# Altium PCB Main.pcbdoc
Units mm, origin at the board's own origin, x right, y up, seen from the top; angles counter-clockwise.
Board outline 147.89 x 80.52 mm, 2 copper layers (Top Layer, Bottom Layer); 32 components, 18 nets, 91 pads, 27 vias.
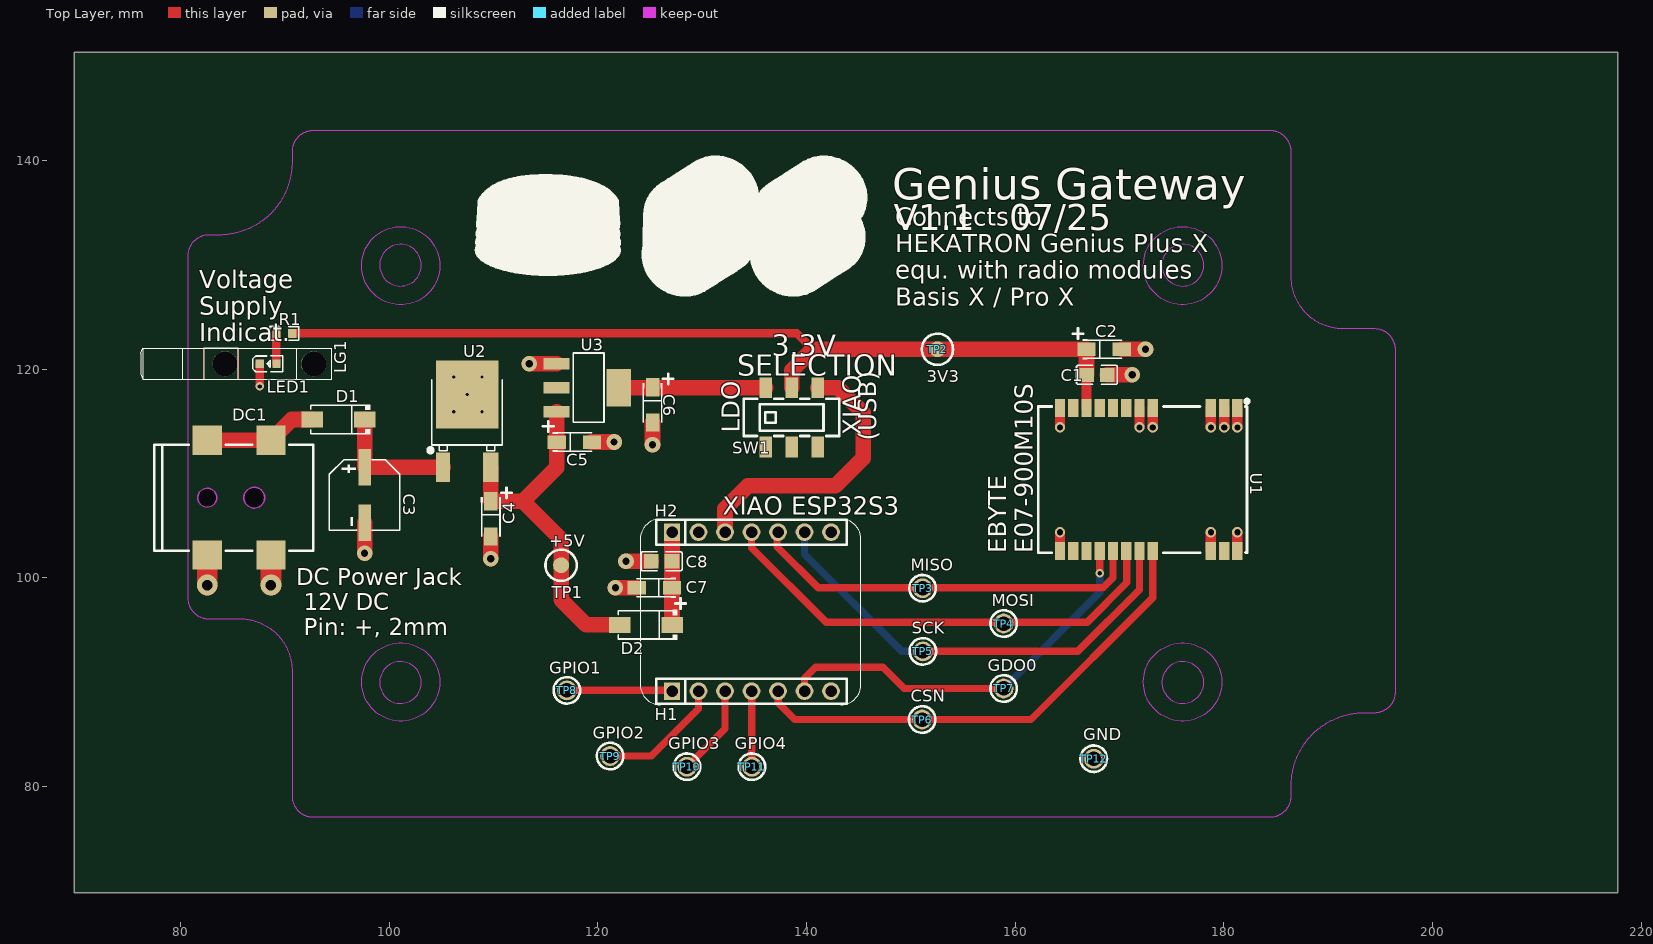
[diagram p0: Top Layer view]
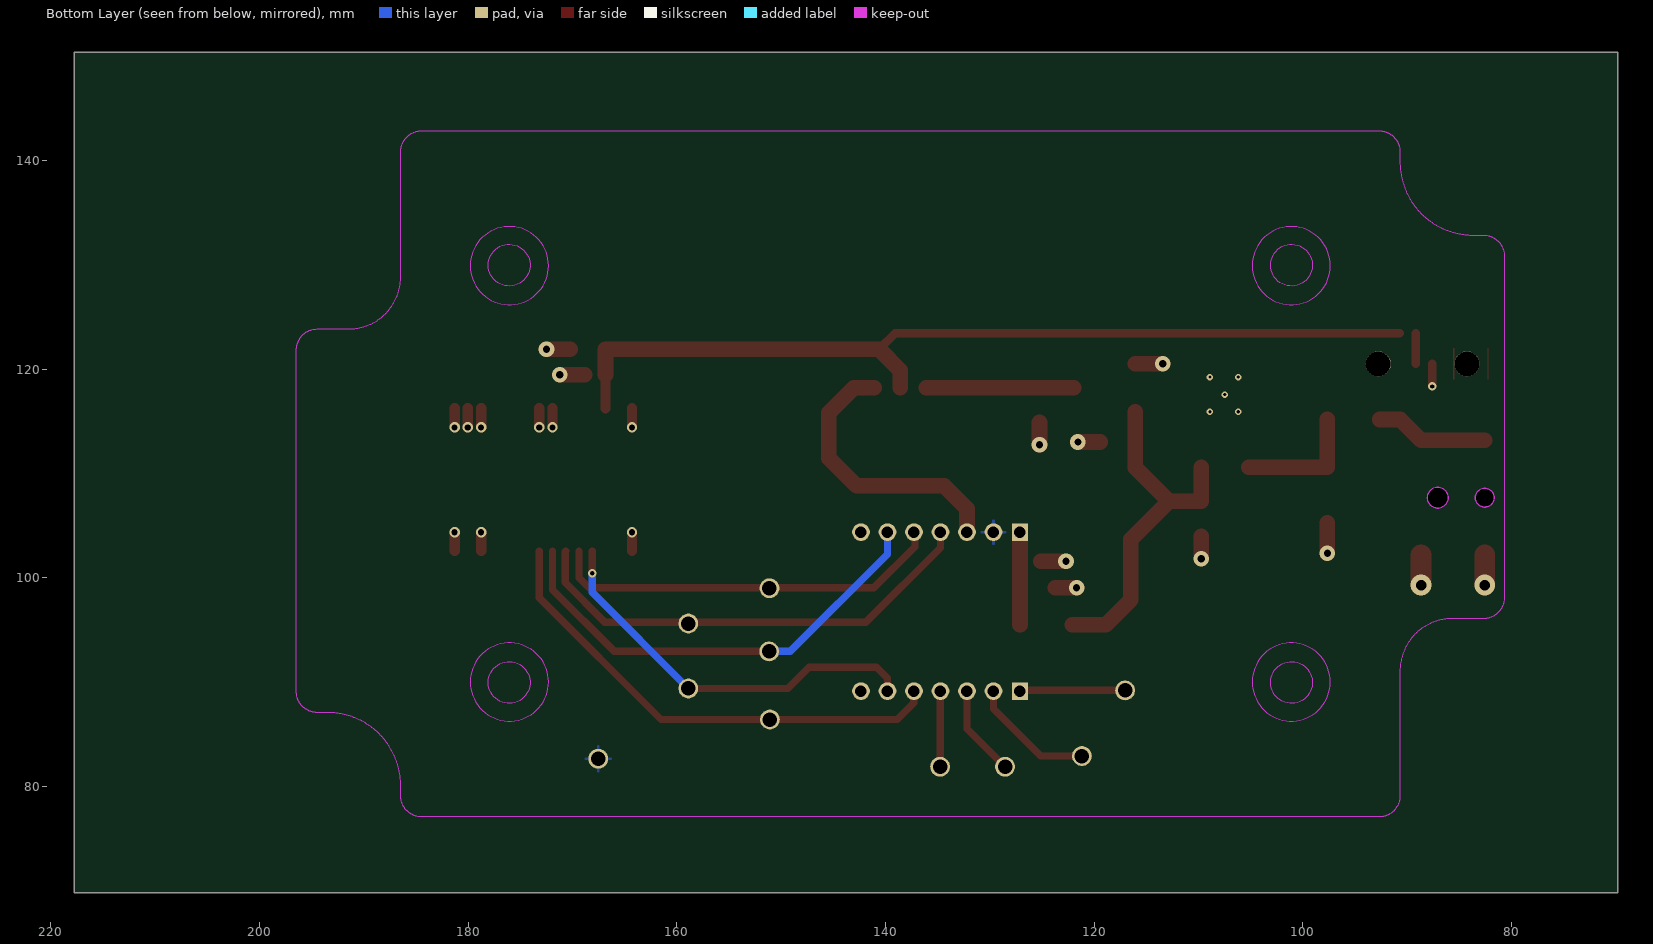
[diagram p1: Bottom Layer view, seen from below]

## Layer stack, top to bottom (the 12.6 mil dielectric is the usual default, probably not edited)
Top Layer: signal copper (thickness not stored)
Dielectric: dielectric 0.32, FR-4, Dk 4.8
Bottom Layer: signal copper (thickness not stored)

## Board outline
217.744,69.85 69.85,69.85 69.85,150.368 217.744,150.368

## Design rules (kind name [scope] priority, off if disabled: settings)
BoardOutlineClearance copperThickness1oz [All] p0: genericclearance=0.254 ignorepadtopadclearanceinfootprint=FALSE except(0: Arc-SplitContinuation Track-SplitContinuation SMDPad-SplitContinuation THPad-SplitContinuation Via-SplitContinuation Fill-SplitContinuation Poly-SplitContinuation Region-SplitContinuation Text-SplitContinuation; 0.152: Track-CutoutEdge SMDPad-CutoutEdge THPad-CutoutEdge Via-CutoutEdge Region-CutoutEdge; 0.3: Track-OutlineEdge SMDPad-OutlineEdge THPad-OutlineEdge Via-OutlineEdge Fill-OutlineEdge Region-OutlineEdge Poly-OutlineEdge Text-OutlineEdge Fill-CutoutEdge)
BoardOutlineClearance copperThickness2oz [All] p0: genericclearance=0.254 ignorepadtopadclearanceinfootprint=FALSE except(0: Arc-SplitContinuation Track-SplitContinuation SMDPad-SplitContinuation THPad-SplitContinuation Via-SplitContinuation Fill-SplitContinuation Poly-SplitContinuation Region-SplitContinuation Text-SplitContinuation; 0.152: Track-CutoutEdge SMDPad-CutoutEdge THPad-CutoutEdge Via-CutoutEdge Region-CutoutEdge; 0.3: Track-OutlineEdge SMDPad-OutlineEdge THPad-OutlineEdge Via-OutlineEdge Fill-OutlineEdge Region-OutlineEdge Poly-OutlineEdge Text-OutlineEdge Fill-CutoutEdge)
Clearance copperThickness1oz [(InNet('+12V') OR InNet('GND') OR InNet('$1N1660') OR InNet('+5V') OR InNet('+12V_IN') OR InNet('+3V3') OR InNet('+3V3-LDO') OR InNet('+3V3-XIAO') OR InNet('SCK') OR InNet('MISO') OR InNet('MOSI') OR InNet('GDO0') OR InNet('CSN') OR InNet('GPIO4') OR InNet('GPIO3') OR InNet('GPIO2') OR InNet('GPIO1') OR InNet('$1N5727'))] p1: gap=0.178 ignorepadtopadclearanceinfootprint=FALSE except(0.102: Track-Track; 0.152: Track-SMDPad SMDPad-SMDPad Track-THPad SMDPad-THPad THPad-THPad Track-Via SMDPad-Via THPad-Via Via-Via SMDPad-Fill THPad-Fill Via-Fill Fill-Fill Track-Region SMDPad-Region THPad-Region Via-Region Region-Region Track-Poly SMDPad-Poly THPad-Poly Via-Poly Fill-Poly Region-Poly Poly-Poly Track-Text SMDPad-Text THPad-Text Via-Text Fill-Text Region-Text Poly-Text Text-Text; 0.175: Track-Hole SMDPad-Hole THPad-Hole Via-Hole Fill-Hole Region-Hole Poly-Hole Text-Hole Sheet-Hole; 0.3: Track-Fill Fill-Region Track-Sheet SMDPad-Sheet THPad-Sheet Via-Sheet Fill-Sheet Region-Sheet Poly-Sheet Text-Sheet)
Clearance copperThickness2oz [All] p1: gap=0.178 ignorepadtopadclearanceinfootprint=FALSE except(0.152: Track-SMDPad SMDPad-SMDPad Track-THPad SMDPad-THPad THPad-THPad Track-Via SMDPad-Via THPad-Via Via-Via SMDPad-Fill THPad-Fill Via-Fill Fill-Fill Track-Region SMDPad-Region THPad-Region Via-Region Region-Region Track-Poly SMDPad-Poly THPad-Poly Via-Poly Fill-Poly Region-Poly Poly-Poly Track-Text SMDPad-Text THPad-Text Via-Text Fill-Text Region-Text Poly-Text Text-Text; 0.175: Track-Hole SMDPad-Hole THPad-Hole Via-Hole Fill-Hole Region-Hole Poly-Hole Text-Hole Sheet-Hole; 0.203: Track-Track; 0.3: Track-Fill Fill-Region Track-Sheet SMDPad-Sheet THPad-Sheet Via-Sheet Fill-Sheet Region-Sheet Poly-Sheet Text-Sheet)
DiffPairsRouting differentialPair [All] p1: maxuncoupledlength=10 minlimit=6 maxlimit=6 mostfreqgap=6 toplayer_minwidth=5 toplayer_prefwidth=10 toplayer_maxwidth=100 bottomlayer_minwidth=5 bottomlayer_prefwidth=10 bottomlayer_maxwidth=100
PasteMaskExpansion pasteMaskExpansion [All] p1: expansion=0
PlaneConnect innerPlane [All] p1: planeconnectstyle=Relief reliefexpansion=0.508 reliefentries=4 reliefconductorwidth=0.254 reliefairgap=0.254
PolygonConnect copperRegion [All] p1: connectstyle=Relief reliefentries=4 reliefconductorwidth=10 polygonreliefangle="90 Angle" airgapwidth=10
RoutingVias viaSize [All] p1: viastyle="Through Hole" holewidth=12.0078 minholewidth=11.811 maxholewidth=248.0314 width=24.0158 minwidth=19.685 maxwidth=393.7008
SolderMaskExpansion solderMaskExpansion [All] p1: useseparateexpansions=TRUE expansion=2 expansionbottom=2
Width copperThickness1oz [All] p1: maxlimit=100 minlimit=5 preferedwidth=10
Width copperThickness2oz [All] p1: maxlimit=100 minlimit=8 preferedwidth=10

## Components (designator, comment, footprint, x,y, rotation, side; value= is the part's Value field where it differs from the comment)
C1 "CC0805KRX7R9BB104" C0805 167.848,119.466 r180 top
C2 "TAJA106K016RNJ" CAP-SMD_L3.2-W1.6-RD-C7171 168.534,121.92 r0 top
C3 "189RV0016" CAP-SMD_BD6.3-L6.6-W6.6-LS7.6-RD 97.658,107.95 r270 top
C4 "TAJA106K016RNJ" CAP-SMD_L3.2-W1.6-RD-C7171 109.759,105.664 r270 top
C5 "TAJA106K016RNJ" CAP-SMD_L3.2-W1.6-RD-C7171 117.76,113.03 r0 top
C6 "TAJA106K016RNJ" CAP-SMD_L3.2-W1.6-RD-C7171 125.253,116.586 r270 top
C7 "TAJA106K016RNJ" CAP-SMD_L3.2-W1.6-RD-C7171 125.435,99.06 r180 top
C8 "CC0805KRX7R9BB104" C0805 126.122,101.6 r0 top
D1 "SS54_C22452" SMA_L4.4-W2.8-LS5.4-R-RD 95.154,115.189 r180 top
D2 "SS54_C22452" SMA_L4.4-W2.8-LS5.4-R-RD 124.618,95.504 r180 top
DC1 "DC-005-5A-2.0-SMT" DC-IN-TH_DC-005-5A-2.0-SMT 85.629,107.696 r0 top
H1 "PM254-1-07-Z-8.5" HDR-TH_7P-P2.54-V-F 134.742,89.154 r0 top
H2 "PM254-1-07-Z-8.5" HDR-TH_7P-P2.54-V-F 134.742,104.394 r0 top
LED1 "KT-0603R" LED0603-RD 88.413,120.523 r0 top
LG1 "Lightguide 1" MENTOR-1271.1000 88.09,120.523 r90 top
R1 "0603WAF5600T5E" R0603 89.966,123.444 r0 top
SW1 "MST22D18G2 125" SW-SMD_MST22D18G2 138.588,115.387 r0 top
TP1 "+5V" Testpoint_SMD_R1.5_Border 116.49,101.219 r0 top
TP2 "3V3" Testpoint_SMD_R1.5_Border 152.558,121.92 r0 top
TP3 "MISO" TEST-TH_BD2.54-P1.39 151.134,99.021 r90 top
TP4 "MOSI" TEST-TH_BD2.54-P1.39 158.908,95.631 r90 top
TP5 "SCK" TEST-TH_BD2.54-P1.39 151.161,92.964 r90 top
TP6 "CSN" TEST-TH_BD2.54-P1.39 151.096,86.433 r90 top
TP7 "GDO0" TEST-TH_BD2.54-P1.39 158.908,89.408 r90 top
TP8 "GPIO1" TEST-TH_BD2.54-P1.39 117.044,89.227 r90 top
TP9 "GPIO2" TEST-TH_BD2.54-P1.39 121.189,82.931 r90 top
TP10 "GPIO3" TEST-TH_BD2.54-P1.39 128.555,81.915 r90 top
TP11 "GPIO4" TEST-TH_BD2.54-P1.39 134.778,81.915 r90 top
TP12 "GND" TEST-TH_BD2.54-P1.39 167.544,82.677 r90 top
U1 "E07-900M10S" WIRELM-SMD_22P-L20.0-W14.0-P1.27-BR 172.808,109.433 r90 top
U2 "L78M05ABDT-TR" TO-252-2_L6.5-W6.1-P4.58-LS10.0-TL 107.473,114.095 r90 top
U3 "AMS1117-3.3_C6186" SOT-223-3_L6.5-W3.4-P2.30-LS7.0-BR 119.03,118.237 r180 top

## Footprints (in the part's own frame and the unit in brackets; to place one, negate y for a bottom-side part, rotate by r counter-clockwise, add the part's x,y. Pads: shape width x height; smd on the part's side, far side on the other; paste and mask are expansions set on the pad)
C0805 [mm]
  rect 1.41x1.35 smd: 1(-1,0) 2(1,0)
  silkscreen extent -1.96,-0.9 1.96,0.9
CAP-SMD_BD6.3-L6.6-W6.6-LS7.6-RD [mm]
  rect 3.5x1.2 smd: 1(-2.67,0) 2(2.67,0)
  silkscreen extent -3.38,-3.38 3.38,3.38
CAP-SMD_L3.2-W1.6-RD-C7171 [mm]
  rect 1.758x1.296 smd: 1(-1.686,0) 2(1.686,0)
  silkscreen extent -3,-0.95 1.68,2
DC-IN-TH_DC-005-5A-2.0-SMT [mm]
  rect 2.8x2.8 smd: 1(-3.05,5.5) 1(3.05,5.5) 2(-3.05,-5.5) 3(3.05,-5.5)
  Board Outline Layer circle w0.005: c1.45,0 r1
  Board Outline Layer circle w0.005: c-3.05,0 r0.9
  Board Outline Layer region: 2.45,0 2.351,-0.434 2.073,-0.782 1.672,-0.975 1.227,-0.975 0.826,-0.782 0.549,-0.434 0.45,0 0.45,0 0.549,0.434 0.826,0.782 1.227,0.975 1.672,0.975 2.073,0.782 2.351,0.434 2.45,0
  Board Outline Layer region: -2.15,0 -2.239,-0.39 -2.489,-0.703 -2.85,-0.877 -3.25,-0.877 -3.611,-0.703 -3.861,-0.39 -3.95,0 -3.95,0 -3.861,0.391 -3.611,0.704 -3.25,0.878 -2.85,0.878 -2.489,0.704 -2.239,0.391 -2.15,0
  Multi-Layer board cut-out: 2.45,0 2.351,-0.434 2.073,-0.782 1.672,-0.975 1.227,-0.975 0.826,-0.782 0.549,-0.434 0.45,0 0.45,0 0.549,0.434 0.826,0.782 1.227,0.975 1.672,0.975 2.073,0.782 2.351,0.434 2.45,0
  Multi-Layer board cut-out: -2.15,0 -2.239,-0.39 -2.489,-0.703 -2.85,-0.877 -3.25,-0.877 -3.611,-0.703 -3.861,-0.39 -3.95,0 -3.95,0 -3.861,0.391 -3.611,0.704 -3.25,0.878 -2.85,0.878 -2.489,0.704 -2.239,0.391 -2.15,0
  silkscreen extent -8.13,-5.08 7.11,5.08
HDR-TH_7P-P2.54-V-F [mm]
  rect 1.575x1.7 hole 1.1: 1(-7.62,0)
  round 1.7 hole 1.1: 2(-5.08,0) 3(-2.54,0) 4(0,0) 5(2.54,0) 6(5.08,0) 7(7.62,0)
  silkscreen extent -9.13,-1.2 9.13,1.2
LED0603-RD [mm]
  rect 0.8x0.8 smd: 1(-0.799,0) 2(0.799,0)
  silkscreen extent -1.49,-0.75 1.39,0.76
MENTOR-1271.1000 [mm]
  round 2.4 hole 2.4 unplated: 0(0,3.8) 0(0,-4.7)
  Top Layer lines w0.1: -1.5,5.84 1.5,5.84 ; -1.5,2.54 1.5,2.54 ; -1.5,2.54 1.5,2.54 ; -1.5,2.54 1.5,2.54
  silkscreen extent -1.5,-6.4 1.5,11.89
R0603 [mm]
  rect 0.806x0.864 smd: 1(-0.753,0) 2(0.753,0)
  silkscreen extent -1.39,-0.66 1.39,0.66
SMA_L4.4-W2.8-LS5.4-R-RD [mm]
  rect 2.063x1.539 smd: 1(2.504,0) 2(-2.504,0)
  silkscreen extent -3.03,-1.43 2.65,1.43
SOT-223-3_L6.5-W3.4-P2.30-LS7.0-BR [mm]
  rect 2.5x1.1 smd: 1(2.97,-2.3) 2(2.97,0) 3(2.97,2.3)
  rect 2.34x3.6 smd: 4(-2.97,0)
  silkscreen extent -1.57,-3.33 1.37,3.33
SW-SMD_MST22D18G2 [mm]
  rect 1.2x2 smd: 1(-2.5,2.85) 2(0,2.85) 3(2.5,2.85) 4(-2.5,-2.85) 5(0,-2.85) 6(2.5,-2.85)
  silkscreen extent -4.6,-1.78 4.57,1.8
TEST-TH_BD2.54-P1.39 [mm]
  round 1.9 hole 1.39: 1(0,0)
  silkscreen extent -1.27,-1.27 1.27,1.27
Testpoint_SMD_R1.5_Border [mil]
  round 60 smd: 1(0,0)
  silkscreen extent -59,-59 59,59
TO-252-2_L6.5-W6.1-P4.58-LS10.0-TL [mm]
  rect 2.8x1.35 smd: 1(-3.475,2.29)
  rect 2.8x1.5 smd: 3(-3.475,-2.29)
  rect 6.5x6 smd: 4(3.475,-0.017)
  silkscreen extent -2.06,-3.39 4.9,3.7
WIRELM-SMD_22P-L20.0-W14.0-P1.27-BR [mm]
  rect 1.7x1 smd: 1(6.85,-8.5) 2(6.85,-7.23) 3(6.85,-5.96) 4(6.85,-0.39) 5(6.85,0.88) 6(6.85,2.15) 7(6.85,3.42) 8(6.85,4.69) 9(6.85,5.96) 10(6.85,7.23) 11(6.85,8.5) 12(-6.85,8.5) 13(-6.85,7.23) 14(-6.85,5.96) 15(-6.85,4.69) 16(-6.85,3.42) 17(-6.85,2.15) 18(-6.85,0.88) 19(-6.85,-0.39) 20(-6.85,-5.96) 21(-6.85,-7.23) 22(-6.85,-8.5)
  silkscreen extent -7,-9.59 7.67,10.58

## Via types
v1: diameter 1, hole 0.6, Top Layer to Bottom Layer, 9 vias
v2: diameter 1.5, hole 0.7, Top Layer to Bottom Layer, 9 vias
v3: diameter 0.61, hole 0.305, Top Layer to Bottom Layer, 5 vias
v4: diameter 0.8, hole 0.4, Top Layer to Bottom Layer, 2 vias
v5: diameter 2, hole 1, Top Layer to Bottom Layer, 2 vias

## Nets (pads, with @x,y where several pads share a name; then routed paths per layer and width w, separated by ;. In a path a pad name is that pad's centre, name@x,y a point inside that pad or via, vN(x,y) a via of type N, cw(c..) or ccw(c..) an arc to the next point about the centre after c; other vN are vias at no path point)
$1N1660: C7.1 C8.2 D2.2 H2.1 | length 8.9
  Top Layer w1.5: D2.2 C7.1 C8.2 H2.1
$1N5727: LED1.2 R1.1 | length 2.9
  Top Layer w0.8: LED1.2@89.206,120.523 R1.1@89.206,123.444
+3V3: C1.2 C2.1 R1.2 SW1.2 TP2.1 U1.9 | length 86.9
  Top Layer w0.8: R1.2@90.713,123.444 139.096,123.444 140.62,121.92
  Top Layer w1: U1.9 C1.2
  Top Layer w1.5: SW1.2 138.588,119.888 140.62,121.92 TP2.1 161.702,121.92 C2.1@166.808,121.92 ; C1.2 C2.1
+3V3-LDO: C6.1 SW1.1 U3.4 | length 14.1
  Top Layer w1.5: U3.4 125.253,118.237 SW1.1
+3V3-XIAO: H2.3 SW1.3 | length 27.2
  Top Layer w1.5: H2.3 132.202,106.644 134.397,108.839 142.779,108.839 145.446,111.506 145.446,115.824 143.033,118.237 SW1.3
+5V: C4.1 C5.1 D2.1 TP1.1 U2.3 U3.3 | length 33.9
  Top Layer w1.5: U2.3 109.763,107.354 C4.1 112.842,107.35 ; U3.3 116.06,113.044 C5.1 116.074,110.582 112.842,107.35 ; D2.1 118.903,95.504 116.49,97.917 116.49,100.838 116.49,103.703 112.842,107.35
+12V: C3.1 D1.2 U2.1 | length 12.1
  Top Layer w1.5: D1.2 C3.1 U2.1
+12V_IN: D1.1 DC1.1 | length 10.9
  Top Layer w1.5: DC1.1@82.579,113.196 88.679,113.196 90.672,115.189 D1.1
CSN: H1.5 TP6.1 U1.19 | length 47.1
  Top Layer w0.7: H1.5@137.318,89.281 137.318,88.011 138.842,86.487 138.896,86.433 TP6.1 161.52,86.433 161.575,86.487 173.198,98.11 U1.19
GDO0: H1.6 TP7.1 U1.15 | length 38.6
  Top Layer w0.7: H1.6 139.822,90.388 140.874,91.44 147.351,91.44 149.383,89.408 TP7.1 ; v4(168.118,100.457) U1.15
  Bottom Layer w0.7: TP7.1 168.118,98.618 v4(168.118,100.457)
GND: C1.1 C2.2 C3.2 C4.2 C5.2 C6.2 C7.2 C8.1 DC1.2 DC1.3 H2.2 LED1.1 TP12.1 U1.1 U1.2 U1.3 U1.4 U1.5 U1.11 U1.12 U1.20 U1.22 U2.4 U3.1 | length 45.5
  Top Layer w0.8: v4(87.607,118.364) LED1.1@87.607,120.523
  Top Layer w1: U1.12 v1(164.308,104.394) ; v1(164.308,114.427) U1.11 ; v1(171.928,114.427) U1.5 ; v1(173.198,114.427) U1.4 ; U1.20 v1(178.768,104.394) ; v1(178.768,114.427) U1.3 ; v1(180.038,114.427) U1.2 ; U1.22 v1(181.308,104.394) ; v1(181.308,114.427) U1.1
  Top Layer w1.5: v2(97.658,102.362) C3.2 ; v2(109.759,101.854) C4.2 ; v2(113.442,120.537) U3.1 ; C5.2 v2(121.57,113.03) ; v2(121.697,99.06) C7.2 ; v2(122.713,101.6) C8.1 ; v2(125.253,112.776) C6.2 ; C1.1 v2(171.227,119.466) ; C2.2 v2(172.497,121.92)
  Top Layer w2: DC1.2 82.581,102.194 v5(82.581,99.314) ; v5(88.679,99.314) DC1.3
  other v3: 106.203,115.928 108.923,115.928 107.49,117.57 106.203,119.253 108.923,119.253
GPIO1: H1.1 TP8.1 | length 10.1
  Top Layer w0.7: TP8.1 127.049,89.227 H1.1
GPIO2: H1.2 TP9.1 | length 12
  Top Layer w0.7: TP9.1 125.126,82.931 129.662,87.467 H1.2
GPIO3: H1.3 TP10.1 | length 8.7
  Top Layer w0.7: TP10.1 132.202,85.562 H1.3
GPIO4: H1.4 TP11.1 | length 7.3
  Top Layer w0.7: H1.4 134.778,89.118 TP11.1
MISO: H2.5 TP3.1 U1.16 | length 38.2
  Top Layer w0.7: H2.5 137.191,104.303 137.191,102.997 141.128,99.06 168.433,99.06 169.388,100.015 U1.16
MOSI: H2.4 TP4.1 U1.17 | length 45
  Top Layer w0.7: H2.4 134.742,102.906 141.89,95.758 166.909,95.758 170.719,99.568 170.719,102.523 U1.17
SCK: H2.6 TP5.1 U1.18 | length 44.2
  Top Layer w0.7: TP5.1 166.02,92.964 171.928,98.872 U1.18
  Bottom Layer w0.7: H2.6 139.822,102.271 149.129,92.964 TP5.1
pads on no net: H1.7 H2.7 LG1.0 SW1.4 SW1.5 SW1.6 U1.6 U1.7 U1.8 U1.10 U1.13 U1.14 U1.21 U3.2

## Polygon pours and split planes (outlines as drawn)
GND on Bottom Layer (solid, remove dead copper, pour order 0): 79.279,144.018 197.262,144.018 197.262,76.2 79.279,76.2

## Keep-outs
Board Outline Layer:
  circle w0.1: c176.078,129.981 r2
  circle w0.1: c176.078,89.983 r2
  circle w0.1: c101.098,129.981 r2
  circle w0.1: c101.098,89.983 r2
  region: 179.803,129.933 cw(c176.053,129.933) 172.303,129.933 cw(c176.053,129.933)
  region: 104.873,129.933 cw(c101.123,129.933) 97.373,129.933 cw(c101.123,129.933)
  region: 104.873,90.031 cw(c101.123,90.031) 97.373,90.031 cw(c101.123,90.031)
  region: 179.803,90.031 cw(c176.053,90.031) 172.303,90.031 cw(c176.053,90.031)
  lines w0.1: 80.708,98.033 80.707,98.097 80.707,130.866 80.708,130.93 80.711,130.994 80.716,131.058 80.723,131.122 80.732,131.185 80.744,131.248 80.757,131.311 80.772,131.373 80.789,131.435 80.809,131.496 80.83,131.557 80.853,131.616 80.878,131.675 80.905,131.734 80.933,131.791 80.964,131.847 80.997,131.902 81.031,131.956 81.067,132.008 81.105,132.059 81.145,132.11 81.186,132.158 81.229,132.206 81.273,132.252 81.319,132.297 81.366,132.34 81.414,132.382 81.463,132.422 81.514,132.461 81.566,132.499 81.619,132.534 81.674,132.568 81.729,132.601 81.785,132.632 81.842,132.66 81.9,132.688 81.959,132.713 82.018,132.737 82.078,132.758 82.139,132.778 82.2,132.796 82.262,132.812 82.325,132.826 82.387,132.838 82.45,132.847 82.514,132.855 82.578,132.861 82.641,132.864 82.706,132.865 83.709,132.865 83.808,132.866 83.907,132.868 84.005,132.872 84.104,132.877 84.203,132.883 84.302,132.891 84.4,132.901 84.499,132.912 84.597,132.924 84.695,132.937 84.792,132.953 84.89,132.969 84.987,132.987 85.084,133.006 85.181,133.027 85.278,133.049 85.374,133.072 85.47,133.096 85.565,133.122 85.66,133.15 85.755,133.178 85.849,133.208 85.943,133.239 86.037,133.272 86.13,133.306 86.222,133.341 86.315,133.377 86.406,133.415 86.497,133.454 86.588,133.494 86.678,133.535 86.767,133.578 86.856,133.622 86.944,133.667 87.031,133.713 87.118,133.76 87.205,133.809 87.29,133.859 87.375,133.91 87.459,133.962 87.542,134.015 87.625,134.07 87.707,134.126 87.788,134.182 87.868,134.24 87.947,134.299 88.026,134.359 88.104,134.421 88.18,134.483 88.256,134.546 88.331,134.611 88.405,134.677 88.478,134.743 88.55,134.811 88.622,134.88 88.692,134.95 88.761,135.021 88.829,135.092 88.896,135.165 88.962,135.239 89.026,135.314 89.09,135.39 89.153,135.467 89.214,135.544 89.275,135.623 89.334,135.702 89.392,135.782 89.449,135.863 89.504,135.945 89.559,136.027 89.612,136.111 89.665,136.195 89.716,136.28 89.765,136.365 89.814,136.451 89.861,136.538 89.908,136.626 89.953,136.714 89.996,136.803 90.039,136.892 90.08,136.982 90.12,137.073 90.159,137.164 90.197,137.255 90.233,137.347 90.268,137.44 90.302,137.533 90.334,137.627 90.365,137.721 90.395,137.815 90.423,137.91 90.45,138.005 90.476,138.101 90.501,138.197 90.524,138.293 90.546,138.389 90.566,138.486 90.585,138.583 90.603,138.681 90.619,138.778 90.634,138.876 90.648,138.974 90.66,139.072 90.671,139.171 90.68,139.269 90.688,139.368 90.695,139.467 90.7,139.566 90.703,139.665 90.705,139.764 90.706,139.863 90.706,140.866 90.707,140.93 90.71,140.994 90.716,141.058 90.723,141.121 90.732,141.185 90.743,141.248 90.757,141.311 90.772,141.373 90.789,141.435 90.808,141.496 90.829,141.556 90.852,141.616 90.877,141.675 90.904,141.733 90.933,141.79 90.964,141.846 90.996,141.901 91.031,141.955 91.067,142.008 91.105,142.059 91.144,142.109 91.186,142.158 91.228,142.205 91.272,142.252 91.318,142.296 91.365,142.34 91.413,142.382 91.463,142.422 91.514,142.461 91.566,142.498 91.619,142.534 91.673,142.568 91.728,142.6 91.785,142.631 91.842,142.66 91.899,142.687 91.958,142.713 92.018,142.736 92.078,142.758 92.138,142.778 92.2,142.796 92.262,142.811 92.324,142.825 92.387,142.837 92.45,142.847 92.513,142.855 92.577,142.86 92.641,142.863 92.705,142.865 184.471,142.865 184.535,142.863 184.599,142.86 184.663,142.855 184.727,142.848 184.79,142.839 184.853,142.827 184.916,142.814 184.978,142.799 185.04,142.782 185.101,142.763 185.161,142.741 185.221,142.718 185.28,142.693 185.338,142.667 185.396,142.638 185.452,142.607 185.506,142.574 185.56,142.54 185.613,142.504 185.664,142.466 185.714,142.426 185.763,142.385 185.811,142.342 185.857,142.298 185.902,142.253 185.945,142.206 185.987,142.157 186.027,142.108 186.066,142.057 186.103,142.005 186.139,141.952 186.173,141.898 186.206,141.842 186.236,141.786 186.265,141.729 186.292,141.671 186.318,141.613 186.341,141.553 186.363,141.493 186.383,141.432 186.401,141.371 186.417,141.309 186.431,141.247 186.442,141.184 186.452,141.121 186.46,141.057 186.465,140.994 186.469,140.93 186.47,140.866 186.47,128.864 186.471,128.765 186.474,128.665 186.479,128.566 186.486,128.467 186.496,128.368 186.507,128.27 186.52,128.171 186.535,128.073 186.553,127.975 186.572,127.878 186.593,127.781 186.616,127.684 186.641,127.588 186.668,127.493 186.696,127.398 186.727,127.303 186.759,127.209 186.793,127.116 186.829,127.023 186.867,126.931 186.907,126.84 186.948,126.75 186.991,126.66 187.036,126.572 187.082,126.484 187.13,126.397 187.18,126.311 187.231,126.226 187.284,126.142 187.339,126.059 187.395,125.977 187.453,125.896 187.512,125.817 187.573,125.738 187.636,125.661 187.7,125.585 187.765,125.511 187.832,125.437 187.9,125.366 187.97,125.295 188.041,125.226 188.114,125.158 188.188,125.092 188.264,125.028 188.34,124.965 188.419,124.903 188.498,124.843 188.579,124.785 188.66,124.729 188.743,124.674 188.827,124.621 188.912,124.569 188.998,124.52 189.085,124.472 189.173,124.425 189.262,124.381 189.351,124.338 189.442,124.297 189.533,124.258 189.625,124.22 189.718,124.185 189.811,124.151 189.905,124.119 190,124.088 190.095,124.06 190.191,124.034 190.287,124.009 190.384,123.986 190.481,123.966 190.579,123.947 190.677,123.93 190.775,123.915 190.873,123.902 190.972,123.891 191.071,123.882 191.17,123.875 191.269,123.87 191.369,123.866 191.468,123.865 194.47,123.865 194.535,123.864 194.599,123.861 194.662,123.856 194.726,123.849 194.79,123.84 194.853,123.828 194.915,123.815 194.978,123.8 195.039,123.783 195.1,123.764 195.161,123.742 195.221,123.719 195.28,123.694 195.338,123.668 195.395,123.639 195.451,123.608 195.506,123.575 195.56,123.541 195.612,123.505 195.664,123.467 195.714,123.427 195.763,123.386 195.81,123.343 195.856,123.299 195.901,123.254 195.944,123.207 195.986,123.158 196.027,123.109 196.066,123.058 196.103,123.006 196.139,122.953 196.173,122.898 196.205,122.843 196.236,122.787 196.265,122.73 196.292,122.672 196.317,122.613 196.341,122.554 196.363,122.494 196.382,122.433 196.4,122.372 196.416,122.31 196.43,122.248 196.442,122.185 196.452,122.122 196.459,122.058 196.465,121.995 196.468,121.931 196.469,121.867 196.469,89.098 196.468,89.034 196.465,88.97 196.46,88.906 196.453,88.842 196.443,88.779 196.432,88.716 196.419,88.653 196.404,88.591 196.387,88.529 196.367,88.468 196.346,88.407 196.323,88.348 196.298,88.289 196.271,88.23 196.242,88.173 196.212,88.117 196.179,88.062 196.145,88.008 196.109,87.956 196.071,87.905 196.031,87.854 195.99,87.806 195.947,87.758 195.903,87.712 195.857,87.667 195.81,87.624 195.762,87.582 195.712,87.542 195.662,87.503 195.61,87.465 195.556,87.43 195.502,87.396 195.447,87.363 195.391,87.332 195.334,87.304 195.276,87.276 195.217,87.251 195.158,87.227 195.098,87.206 195.037,87.186 194.976,87.168 194.914,87.152 194.851,87.138 194.789,87.126 194.726,87.117 194.662,87.109 194.598,87.103 194.534,87.1 194.47,87.099 193.467,87.099 193.368,87.098 193.269,87.096 193.17,87.092 193.072,87.087 192.973,87.081 192.874,87.073 192.776,87.063 192.677,87.052 192.579,87.04 192.481,87.027 192.383,87.011 192.286,86.995 192.189,86.977 192.092,86.958 191.995,86.937 191.898,86.915 191.802,86.892 191.706,86.868 191.611,86.842 191.516,86.814 191.421,86.786 191.327,86.756 191.233,86.725 191.139,86.692 191.046,86.658 190.953,86.623 190.861,86.587 190.77,86.549 190.679,86.51 190.588,86.47 190.498,86.429 190.409,86.386 190.32,86.342 190.232,86.297 190.144,86.251 190.058,86.204 189.971,86.155 189.886,86.105 189.801,86.054 189.717,86.002 189.634,85.949 189.551,85.894 189.469,85.838 189.388,85.782 189.308,85.724 189.229,85.665 189.15,85.605 189.072,85.543 188.996,85.481 188.92,85.418 188.845,85.353 188.771,85.287 188.698,85.221 188.626,85.153 188.554,85.084 188.484,85.014 188.415,84.943 188.347,84.872 188.28,84.799 188.214,84.725 188.149,84.65 188.086,84.574 188.023,84.497 187.962,84.42 187.901,84.341 187.842,84.262 187.784,84.182 187.727,84.101 187.672,84.019 187.617,83.937 187.564,83.853 187.511,83.769 187.46,83.684 187.411,83.599 187.362,83.513 187.314,83.426 187.268,83.338 187.223,83.25 187.179,83.161 187.137,83.072 187.096,82.982 187.056,82.891 187.017,82.8 186.979,82.709 186.943,82.617 186.908,82.524 186.874,82.431 186.842,82.337 186.811,82.243 186.781,82.149 186.753,82.054 186.725,81.959 186.7,81.863 186.675,81.767 186.652,81.671 186.63,81.575 186.61,81.478 186.591,81.381 186.573,81.283 186.557,81.186 186.542,81.088 186.528,80.99 186.516,80.892 186.505,80.793 186.496,80.695 186.488,80.596 186.481,80.497 186.476,80.398 186.473,80.299 186.47,80.2 186.47,80.101 186.47,79.098 186.469,79.034 186.466,78.97 186.46,78.906 186.453,78.843 186.444,78.779 186.433,78.716 186.419,78.653 186.404,78.591 186.387,78.529 186.368,78.468 186.347,78.408 186.324,78.348 186.299,78.289 186.272,78.231 186.243,78.174 186.212,78.118 186.18,78.063 186.145,78.009 186.109,77.956 186.071,77.905 186.032,77.855 185.99,77.806 185.948,77.759 185.904,77.712 185.858,77.668 185.811,77.624 185.763,77.582 185.713,77.542 185.662,77.503 185.61,77.466 185.557,77.43 185.503,77.396 185.448,77.364 185.391,77.333 185.334,77.304 185.276,77.277 185.218,77.251 185.158,77.228 185.098,77.206 185.037,77.186 184.976,77.168 184.914,77.153 184.852,77.139 184.789,77.127 184.726,77.117 184.663,77.109 184.599,77.104 184.535,77.101 184.471,77.099 92.705,77.099 92.641,77.101 92.577,77.104 92.513,77.109 92.449,77.116 92.386,77.125 92.323,77.137 92.26,77.15 92.198,77.165 92.136,77.182 92.075,77.201 92.015,77.223 91.955,77.246 91.896,77.271 91.838,77.297 91.78,77.326 91.724,77.357 91.669,77.39 91.616,77.424 91.563,77.46 91.512,77.498 91.462,77.538 91.413,77.579 91.365,77.622 91.319,77.666 91.274,77.711 91.231,77.758 91.189,77.807 91.149,77.856 91.11,77.907 91.073,77.959 91.037,78.012 91.003,78.066 90.97,78.122 90.94,78.178 90.911,78.235 90.884,78.293 90.858,78.351 90.835,78.411 90.813,78.471 90.793,78.532 90.775,78.593 90.759,78.655 90.745,78.717 90.734,78.78 90.724,78.843 90.716,78.907 90.711,78.97 90.707,79.034 90.706,79.098 90.706,91.1 90.705,91.199 90.702,91.299 90.697,91.398 90.69,91.497 90.68,91.596 90.669,91.694 90.656,91.793 90.64,91.891 90.623,91.989 90.604,92.086 90.583,92.183 90.56,92.28 90.535,92.376 90.508,92.471 90.479,92.566 90.449,92.661 90.417,92.755 90.382,92.848 90.346,92.941 90.309,93.033 90.269,93.124 90.228,93.214 90.185,93.304 90.14,93.392 90.094,93.48 90.046,93.567 89.996,93.653 89.945,93.738 89.892,93.822 89.837,93.905 89.781,93.987 89.723,94.068 89.664,94.147 89.603,94.226 89.54,94.303 89.476,94.379 89.411,94.453 89.344,94.527 89.276,94.598 89.206,94.669 89.135,94.738 89.062,94.806 88.988,94.872 88.912,94.936 88.835,94.999 88.757,95.061 88.678,95.121 88.597,95.179 88.516,95.235 88.433,95.29 88.349,95.343 88.264,95.395 88.178,95.444 88.091,95.492 88.003,95.539 87.914,95.583 87.825,95.626 87.734,95.667 87.643,95.706 87.551,95.744 87.458,95.779 87.365,95.813 87.271,95.845 87.176,95.876 87.081,95.904 86.985,95.93 86.889,95.955 86.792,95.978 86.695,95.998 86.597,96.017 86.499,96.034 86.401,96.049 86.302,96.062 86.204,96.073 86.105,96.082 86.006,96.089 85.906,96.094 85.807,96.098 85.708,96.099 82.706,96.099 82.641,96.1 82.577,96.103 82.514,96.108 82.45,96.115 82.386,96.124 82.323,96.136 82.261,96.149 82.198,96.164 82.137,96.181 82.075,96.2 82.015,96.222 81.955,96.245 81.896,96.27 81.838,96.297 81.781,96.325 81.725,96.356 81.67,96.389 81.616,96.423 81.564,96.459 81.512,96.497 81.462,96.537 81.413,96.578 81.366,96.621 81.32,96.665 81.275,96.71 81.231,96.757 81.19,96.806 81.149,96.855 81.11,96.906 81.073,96.958 81.037,97.011 81.003,97.066 80.971,97.121 80.94,97.177 80.911,97.234 80.884,97.292 80.859,97.351 80.835,97.41 80.813,97.47 80.794,97.531 80.776,97.592 80.76,97.654 80.746,97.716 80.734,97.779 80.724,97.842 80.717,97.906 80.711,97.969 80.708,98.033

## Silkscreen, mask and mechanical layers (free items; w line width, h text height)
Top Silkscreen Layer:
  drawing of 15 lines, arcs and shapes, not listed
  text "Genius Gateway" at 148.24,136.271 h3
  text "V1.1   07/25" at 148.367,133.35 h2.5
  text "Connects to / HEKATRON Genius Plus X / equ. with radio modules / Basis X / Pro X" at 148.494,126.111 h1.7
  text "Voltage / Supply / Indicat." at 81.819,122.682 h1.7
  text "3.3V" at 136.683,121.285 h2
  text "SELECTION" at 133.381,119.38 h2
  text "LDO" at 133.635,113.919 h1.7 r90
  text "XIAO" at 145.192,113.665 h1.7 r90
  text "(USB)" at 146.716,113.157 h1.7 r90
  text "XIAO ESP32S3" at 131.984,106.045 h1.7
  text "EBYTE / E07-900M10S" at 161.702,102.362 h1.7 r90
  text "DC Power Jack /  12V DC /  Pin: +, 2mm" at 91.09,94.488 h1.6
